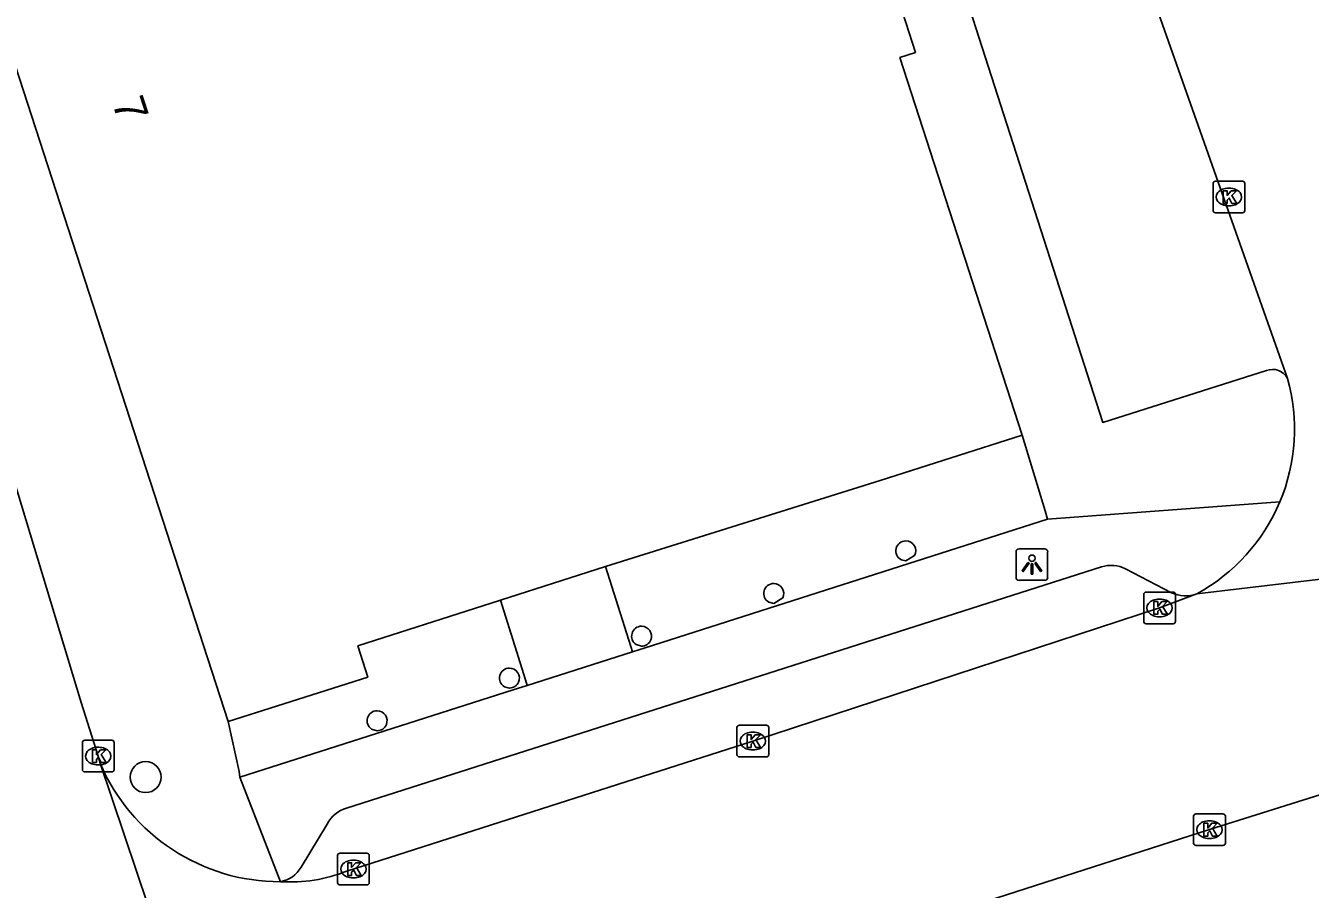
# Model space of a CAD drawing. Extents: x 159503 to 160347, y 382525 to 383272.
# Drawn here: x 159551.45 to 159591.98, y 382903.28 to 382930.55 of the extents above; entities that cross this region are included whole.
import ezdxf

# ---------------------------------------------------------------- set-up
doc = ezdxf.new("R2010")
doc.units = 0
for name, color, linetype in [('IMGEO_Boom', 7, 'Continuous'), ('IMGEO_Kolk', 7, 'Continuous'), ('IMGEO_Lichtpunt', 7, 'Continuous'), ('IMGEO_Pand', 7, 'Continuous'), ('IMGEO_Pand_nummerreeks', 7, 'Continuous'), ('IMGEO_Rijbaan_lokaal_open', 7, 'Continuous'), ('IMGEO_Voetpad_open', 7, 'Continuous')]:
    doc.layers.add(name, color=color, linetype=linetype)

msp = doc.modelspace()

# ---------------------------------------------------------------- linework, layer by layer
at = {"layer": 'IMGEO_Boom'}
msp.add_circle((159555.236, 382906.827), 0.489, dxfattribs=at)
at = {"layer": 'IMGEO_Kolk'}
for p, q in [((159588.916, 382924.714), (159588.916, 382925.566)), ((159588.991, 382925.64), (159589.843, 382925.64)), ((159589.917, 382925.566), (159589.917, 382924.714)), ((159589.404, 382925.42), (159589.429, 382925.42)), ((159589.427, 382924.86), (159589.402, 382924.86)), ((159589.843, 382924.64), (159588.991, 382924.64)), ((159586.728, 382911.742), (159586.728, 382912.594)), ((159586.803, 382912.668), (159587.655, 382912.668)), ((159587.729, 382912.594), (159587.729, 382911.742)), ((159587.216, 382912.448), (159587.241, 382912.448)), ((159587.239, 382911.888), (159587.214, 382911.888)), ((159587.655, 382911.668), (159586.803, 382911.668)), ((159573.894, 382907.539), (159573.894, 382908.391)), ((159573.969, 382908.465), (159574.821, 382908.465)), ((159574.382, 382908.245), (159574.407, 382908.245)), ((159574.895, 382908.391), (159574.895, 382907.539)), ((159553.241, 382907.064), (159553.241, 382907.916)), ((159553.316, 382907.99), (159554.168, 382907.99)), ((159553.729, 382907.77), (159553.754, 382907.77)), ((159554.242, 382907.916), (159554.242, 382907.064)), ((159574.821, 382907.465), (159573.969, 382907.465)), ((159574.405, 382907.685), (159574.38, 382907.685)), ((159554.168, 382906.99), (159553.316, 382906.99)), ((159553.752, 382907.21), (159553.727, 382907.21)), ((159588.302, 382904.742), (159588.302, 382905.594)), ((159588.377, 382905.668), (159589.229, 382905.668)), ((159588.79, 382905.448), (159588.815, 382905.448)), ((159589.303, 382905.594), (159589.303, 382904.742)), ((159589.229, 382904.668), (159588.377, 382904.668)), ((159588.813, 382904.888), (159588.788, 382904.888)), ((159561.292, 382903.499), (159561.292, 382904.351)), ((159561.367, 382904.425), (159562.219, 382904.425)), ((159561.78, 382904.205), (159561.805, 382904.205)), ((159562.293, 382904.351), (159562.293, 382903.499)), ((159562.219, 382903.425), (159561.367, 382903.425)), ((159561.803, 382903.645), (159561.778, 382903.645))]:
    msp.add_line(p, q, dxfattribs=at)
for points in [[(159588.916, 382924.714), (159588.916, 382925.566)], [(159588.991, 382925.64), (159589.843, 382925.64)], [(159589.917, 382925.566), (159589.917, 382924.714)], [(159589.237, 382925.34), (159589.36, 382925.34), (159589.36, 382925.189), (159589.49, 382925.34), (159589.654, 382925.34), (159589.508, 382925.189), (159589.661, 382924.94), (159589.509, 382924.94), (159589.424, 382925.104), (159589.36, 382925.037), (159589.36, 382924.94), (159589.237, 382924.94), (159589.237, 382925.34)], [(159589.843, 382924.64), (159588.991, 382924.64)], [(159586.728, 382911.742), (159586.728, 382912.594)], [(159586.803, 382912.668), (159587.655, 382912.668)], [(159587.729, 382912.594), (159587.729, 382911.742)], [(159587.049, 382912.368), (159587.172, 382912.368), (159587.172, 382912.217), (159587.302, 382912.368), (159587.466, 382912.368), (159587.32, 382912.217), (159587.473, 382911.968), (159587.321, 382911.968), (159587.236, 382912.132), (159587.172, 382912.065), (159587.172, 382911.968), (159587.049, 382911.968), (159587.049, 382912.368)], [(159587.655, 382911.668), (159586.803, 382911.668)], [(159573.894, 382907.539), (159573.894, 382908.391)], [(159573.969, 382908.465), (159574.821, 382908.465)], [(159574.215, 382908.165), (159574.338, 382908.165), (159574.338, 382908.014), (159574.468, 382908.165), (159574.632, 382908.165), (159574.486, 382908.014), (159574.639, 382907.765), (159574.487, 382907.765), (159574.402, 382907.929), (159574.338, 382907.862), (159574.338, 382907.765), (159574.215, 382907.765), (159574.215, 382908.165)], [(159574.895, 382908.391), (159574.895, 382907.539)], [(159553.241, 382907.064), (159553.241, 382907.916)], [(159553.316, 382907.99), (159554.168, 382907.99)], [(159554.242, 382907.916), (159554.242, 382907.064)], [(159553.562, 382907.69), (159553.685, 382907.69), (159553.685, 382907.539), (159553.815, 382907.69), (159553.979, 382907.69), (159553.833, 382907.539), (159553.986, 382907.29), (159553.834, 382907.29), (159553.749, 382907.454), (159553.685, 382907.387), (159553.685, 382907.29), (159553.562, 382907.29), (159553.562, 382907.69)], [(159574.821, 382907.465), (159573.969, 382907.465)], [(159554.168, 382906.99), (159553.316, 382906.99)], [(159588.302, 382904.742), (159588.302, 382905.594)], [(159588.377, 382905.668), (159589.229, 382905.668)], [(159588.623, 382905.368), (159588.746, 382905.368), (159588.746, 382905.217), (159588.876, 382905.368), (159589.04, 382905.368), (159588.894, 382905.217), (159589.047, 382904.968), (159588.895, 382904.968), (159588.81, 382905.132), (159588.746, 382905.065), (159588.746, 382904.968), (159588.623, 382904.968), (159588.623, 382905.368)], [(159589.303, 382905.594), (159589.303, 382904.742)], [(159589.229, 382904.668), (159588.377, 382904.668)], [(159561.292, 382903.499), (159561.292, 382904.351)], [(159561.367, 382904.425), (159562.219, 382904.425)], [(159561.613, 382904.125), (159561.736, 382904.125), (159561.736, 382903.974), (159561.866, 382904.125), (159562.03, 382904.125), (159561.884, 382903.974), (159562.037, 382903.725), (159561.885, 382903.725), (159561.8, 382903.889), (159561.736, 382903.822), (159561.736, 382903.725), (159561.613, 382903.725), (159561.613, 382904.125)], [(159562.293, 382904.351), (159562.293, 382903.499)], [(159562.219, 382903.425), (159561.367, 382903.425)]]:
    msp.add_lwpolyline(points, dxfattribs=at)
for centre, start, end in [((159588.993, 382925.564), 91.552, 178.448), ((159588.993, 382925.564), 91.552, 178.448), ((159589.841, 382925.564), 1.552, 88.448), ((159589.841, 382925.564), 1.552, 88.448), ((159588.993, 382924.716), 181.552, 268.448), ((159588.993, 382924.716), 181.552, 268.448), ((159589.841, 382924.716), 271.552, 358.448), ((159589.841, 382924.716), 271.552, 358.448), ((159586.805, 382912.592), 91.552, 178.448), ((159586.805, 382912.592), 91.552, 178.448), ((159587.653, 382912.592), 1.552, 88.448), ((159587.653, 382912.592), 1.552, 88.448), ((159586.805, 382911.744), 181.552, 268.448), ((159586.805, 382911.744), 181.552, 268.448), ((159587.653, 382911.744), 271.552, 358.448), ((159587.653, 382911.744), 271.552, 358.448), ((159573.971, 382908.389), 91.552, 178.448), ((159573.971, 382908.389), 91.552, 178.448), ((159574.819, 382908.389), 1.552, 88.448), ((159574.819, 382908.389), 1.552, 88.448), ((159553.318, 382907.914), 91.552, 178.448), ((159553.318, 382907.914), 91.552, 178.448), ((159554.166, 382907.914), 1.552, 88.448), ((159554.166, 382907.914), 1.552, 88.448), ((159573.971, 382907.541), 181.552, 268.448), ((159573.971, 382907.541), 181.552, 268.448), ((159574.819, 382907.541), 271.552, 358.448), ((159574.819, 382907.541), 271.552, 358.448), ((159553.318, 382907.066), 181.552, 268.448), ((159553.318, 382907.066), 181.552, 268.448), ((159554.166, 382907.066), 271.552, 358.448), ((159554.166, 382907.066), 271.552, 358.448), ((159588.379, 382905.592), 91.552, 178.448), ((159588.379, 382905.592), 91.552, 178.448), ((159589.227, 382905.592), 1.552, 88.448), ((159589.227, 382905.592), 1.552, 88.448), ((159588.379, 382904.744), 181.552, 268.448), ((159588.379, 382904.744), 181.552, 268.448), ((159589.227, 382904.744), 271.552, 358.448), ((159589.227, 382904.744), 271.552, 358.448), ((159561.369, 382904.349), 91.552, 178.448), ((159561.369, 382904.349), 91.552, 178.448), ((159562.217, 382904.349), 1.552, 88.448), ((159562.217, 382904.349), 1.552, 88.448), ((159561.369, 382903.501), 181.552, 268.448), ((159561.369, 382903.501), 181.552, 268.448), ((159562.217, 382903.501), 271.552, 358.448), ((159562.217, 382903.501), 271.552, 358.448)]:
    msp.add_arc(centre, 0.0765, start, end, dxfattribs=at)
for centre, major_axis, ratio, start_param, end_param in [((159589.403, 382925.14), (-0.387, 0.002), 0.722429, 4.712389, 7.853982), ((159589.428, 382925.14), (-0.39, 0.002), 0.717154, 1.570796, 4.712389), ((159587.215, 382912.168), (-0.387, 0.002), 0.722429, 4.712389, 7.853982), ((159587.24, 382912.168), (-0.39, 0.002), 0.717154, 1.570796, 4.712389), ((159574.381, 382907.965), (-0.387, 0.002), 0.722429, 4.712389, 7.853982), ((159574.406, 382907.965), (-0.39, 0.002), 0.717154, 1.570796, 4.712389), ((159553.728, 382907.49), (-0.387, 0.002), 0.722429, 4.712389, 7.853982), ((159553.753, 382907.49), (-0.39, 0.002), 0.717154, 1.570796, 4.712389), ((159588.789, 382905.168), (-0.387, 0.002), 0.722429, 4.712389, 7.853982), ((159588.814, 382905.168), (-0.39, 0.002), 0.717154, 1.570796, 4.712389), ((159561.779, 382903.925), (-0.387, 0.002), 0.722429, 4.712389, 7.853982), ((159561.804, 382903.925), (-0.39, 0.002), 0.717154, 1.570796, 4.712389)]:
    msp.add_ellipse(centre, major_axis=major_axis, ratio=ratio, start_param=start_param, end_param=end_param, dxfattribs=at)
at = {"layer": 'IMGEO_Lichtpunt'}
for p, q in [((159582.701, 382913.94), (159582.701, 382913.133)), ((159582.701, 382913.94), (159582.701, 382913.133)), ((159583.603, 382914.035), (159582.795, 382914.035)), ((159583.603, 382914.035), (159582.795, 382914.035)), ((159583.697, 382913.133), (159583.697, 382913.94)), ((159583.697, 382913.133), (159583.697, 382913.94)), ((159582.795, 382913.039), (159583.603, 382913.039)), ((159582.795, 382913.039), (159583.603, 382913.039))]:
    msp.add_line(p, q, dxfattribs=at)
for points in [[(159583.075, 382913.604), (159583.114, 382913.576), (159582.926, 382913.314), (159582.888, 382913.341), (159583.075, 382913.604)], [(159583.177, 382913.556), (159583.224, 382913.556), (159583.224, 382913.234), (159583.177, 382913.234), (159583.177, 382913.556)], [(159583.287, 382913.576), (159583.325, 382913.603), (159583.512, 382913.341), (159583.473, 382913.313), (159583.287, 382913.576)]]:
    msp.add_lwpolyline(points, dxfattribs=at)
msp.add_circle((159583.2, 382913.738), 0.0994, dxfattribs=at)
for centre, start, end in [((159582.795, 382913.94), 90, 180), ((159582.795, 382913.94), 90, 180), ((159583.603, 382913.94), 0, 90), ((159583.603, 382913.94), 0, 90), ((159582.795, 382913.133), 180, 270), ((159582.795, 382913.133), 180, 270), ((159583.603, 382913.133), 270, 0), ((159583.603, 382913.133), 270, 360)]:
    msp.add_arc(centre, 0.0946, start, end, dxfattribs=at)
at = {"layer": 'IMGEO_Pand'}
for points in [[(159578.31, 382933.501), (159579.526, 382929.703), (159579.035, 382929.541), (159582.89, 382917.624)], [(159557.842, 382908.578), (159550.597, 382930.894)], [(159569.741, 382913.479), (159578.417, 382916.191), (159582.89, 382917.624)], [(159579.08, 382913.687), (159579.221, 382913.654), (159579.499, 382913.821)], [(159566.429, 382912.413), (159569.741, 382913.479)], [(159557.842, 382908.578), (159562.246, 382909.987), (159561.933, 382910.967), (159566.429, 382912.413)], [(159574.898, 382912.349), (159575.053, 382912.309), (159575.338, 382912.49)], [(159570.716, 382911.011), (159570.885, 382910.962)], [(159566.557, 382909.681), (159566.716, 382909.638)], [(159562.367, 382908.341), (159562.538, 382908.29)]]:
    msp.add_lwpolyline(points, dxfattribs=at)
for centre, radius, start, end in [((159579.221, 382913.969), 0.315, 89.9509, 243.4718), ((159579.221, 382913.969), 0.315, 331.999, 89.9649), ((159575.053, 382912.624), 0.315, 89.9885, 240.5722), ((159575.053, 382912.624), 0.315, 334.7544, 90.0558), ((159570.886, 382911.277), 0.315, 90.1205, 237.4424), ((159570.885, 382911.277), 0.315, 338.0518, 89.9369), ((159570.884, 382911.278), 0.316, 270.1114, 337.9003), ((159566.716, 382909.953), 0.315, 90.0381, 239.65), ((159566.715, 382909.953), 0.315, 335.873, 89.8839), ((159566.715, 382909.954), 0.316, 270.2247, 335.6685), ((159562.538, 382908.605), 0.315, 89.9952, 237.0972), ((159562.539, 382908.605), 0.315, 338.3083, 90.1086), ((159562.539, 382908.604), 0.314, 269.8096, 338.5576)]:
    msp.add_arc(centre, radius, start, end, dxfattribs=at)
at = {"layer": 'IMGEO_Rijbaan_lokaal_open'}
for points in [[(159583.137, 382942.457), (159591.263, 382919.413)], [(159553.797, 382907.263), (159553.741, 382907.489), (159553.201, 382909.181), (159550.348, 382918.574), (159550.079, 382919.415)], [(159605.385, 382912.009), (159597.46, 382913.683), (159588.407, 382912.617)], [(159588.407, 382912.617), (159587.229, 382912.17), (159574.395, 382907.966), (159561.584, 382903.86)], [(159559.092, 382891.532), (159553.797, 382907.263)], [(159571.873, 382899.757), (159576.904, 382901.342), (159588.802, 382905.17), (159592.483, 382906.334)]]:
    msp.add_lwpolyline(points, dxfattribs=at)
for centre, radius, start, end in [((159585.57, 382917.807), 5.915, 337.2008, 15.7526), ((159585.57, 382917.808), 5.915, 298.6594, 337.1961), ((159559.468, 382909.697), 6.171, 203.2297, 270.1791), ((159559.79, 382908.373), 4.857, 266.423, 291.6766)]:
    msp.add_arc(centre, radius, start, end, dxfattribs=at)
at = {"layer": 'IMGEO_Voetpad_open'}
for points in [[(159590.597, 382919.659), (159585.433, 382918.024), (159578.122, 382940.788)], [(159582.89, 382917.624), (159583.616, 382915.235), (159583.696, 382914.972)], [(159583.696, 382914.972), (159591.023, 382915.515)], [(159583.696, 382914.972), (159571.002, 382910.912), (159570.596, 382910.786)], [(159585.398, 382913.461), (159561.575, 382905.846)], [(159569.741, 382913.479), (159570.542, 382910.955), (159570.596, 382910.786)], [(159587.605, 382912.648), (159586.15, 382913.405)], [(159567.278, 382909.721), (159567.223, 382909.894), (159566.429, 382912.413)], [(159570.596, 382910.786), (159567.278, 382909.721)], [(159558.21, 382906.821), (159566.835, 382909.579), (159567.278, 382909.721)], [(159558.21, 382906.821), (159558.186, 382907.003), (159557.842, 382908.578)], [(159559.487, 382903.526), (159558.21, 382906.821)], [(159560.968, 382905.346), (159560.14, 382903.985)]]:
    msp.add_lwpolyline(points, dxfattribs=at)
for centre, radius, start, end in [((159590.796, 382919.173), 0.525, 27.1829, 112.2717), ((159585.707, 382912.528), 0.982, 63.1709, 108.3114), ((159588.043, 382913.591), 1.04, 245.0853, 290.4875), ((159561.819, 382904.932), 0.946, 104.9179, 154.0402), ((159559.329, 382904.445), 0.932, 279.7562, 330.4513)]:
    msp.add_arc(centre, radius, start, end, dxfattribs=at)

# ---------------------------------------------------------------- texts
at = {"layer": 'IMGEO_Pand_nummerreeks'}
msp.add_text('7', height=1, rotation=287.9161, dxfattribs=at).set_placement((159554.171, 382928.124))

doc.saveas('drawing.dxf')
